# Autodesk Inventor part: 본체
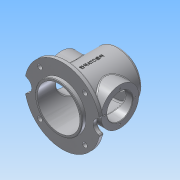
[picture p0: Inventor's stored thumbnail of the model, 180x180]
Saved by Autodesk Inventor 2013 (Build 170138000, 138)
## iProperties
Created: 2018-04
Part Number: 본체
Material: 알루미늄 6061
Document SubType Name: Modeling
Designer: Administrator
Density: 2.71 g/cm^3
Mass: 1151.24 g
Surface Area: 1200.36 cm^2
Volume: 424.812 cm^3
Author: Administrator
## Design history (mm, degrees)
sketch "스케치1"
  geometry: C1 r 50 at (0, 0); 1 further point
  constraints: 1 centre point, 1 coincident
  dimensions: "d1" = 100 diameter of C1
extrude "돌출1" new body sketch "스케치1" distance "d2" = 128; taper "d3" = 0 deg
hole "구멍1" diameter "d6" = 90; stored, may be unused: countersink angle "d10" = 90 deg, drill point angle "d12" = 0 deg; dims "d4" = 10, "d5" = 10, "d7" = 6, "d8" = 4, "d9" = 2, "d11" = 120
node "작업 평면1"
sketch "스케치2"
  geometry: C1 r 80 at (0, 0); C2 r 50 at (0, 0) reference; 1 further point
  constraints: 1 centre point, 1 coincident
  dimensions: "d14" = 160 diameter of C1
extrude "돌출2" join sketch "스케치2" distance "d15" = 10; taper "d16" = 0 deg
sketch "스케치3"
  geometry: C1 r 50 at (0, 0) reference; C2 r 15 at (-80, 0); C3 r 15 at (80, 0); A1 r 80 centre (0, 0) between (-80, 0) and (80, 0) reference
  constraints: 2 centre point, 2 horizontal alignment, 2 point on circle
  dimensions: "d17" = 30 diameter of C2; "d18" = 30 diameter of C3
extrude "돌출3" cut sketch "스케치3" stored distance "d19" = 10; taper "d20" = 0 deg
sketch "스케치4" dims "d21" = 135
  geometry: L1 (0, 50)-(0, 0); L2 (0, 0)-(-47.73, 47.73); C1 r 5 at (-47.73, 47.73); A1 r 80 centre (0, 0) between (78.594, 14.934) and (-78.594, 14.934) reference; 1 further point
  constraints: 4 end point, 2 coincident, 1 centre point, 1 vertical, 1 vertical alignment, 4 other
  dimensions: "d22" = 45 deg angle of L2 L1; "d24" = 10 diameter of C1
extrude "돌출4" cut sketch "스케치4" stored distance "d25" = 10; taper "d26" = 0 deg
node "작업 평면2"
sketch "스케치5"
  geometry: L1 (8, -14.934)-(8, -80) reference; C1 r 40 at (68, 0); 1 further point
  constraints: 1 centre point, 1 horizontal alignment
  dimensions: "d31" = 80 diameter of C1; "d33" = 60 distance from line of L1 C1.centre
extrude "돌출5" join sketch "스케치5" stored distance "d34" = 10; taper "d35" = 0 deg
sketch "스케치6"
  geometry: C1 r 40 at (0, 0) reference; 2 further points
  constraints: 1 coincident
hole "구멍2" sketch "스케치6" at (0, 0) diameter "d36" = 54; stored, may be unused: countersink angle "d40" = 90 deg, drill point angle "d42" = 0 deg; dims "d37" = 6, "d38" = 4, "d39" = 2, "d41" = 120
sketch "스케치7"
  geometry: C1 r 27 at (0, 0) reference; 2 further points
  constraints: 1 vertical alignment
  dimensions: "d43" = 32.5 distance of point (0, 32.5) C1.centre
hole "구멍3" sketch "스케치7" at (0, 32.5) diameter "d44" = 3.242; stored, may be unused: countersink angle "d48" = 90 deg, drill point angle "d50" = 118 deg; dims "d45" = 8, "d46" = 4, "d47" = 2, "d49" = 10
sketch "스케치8"
  geometry: C1 r 50 at (0, 0) reference; C2 r 40 at (0, 0)
  constraints: 1 centre point, 1 coincident
  dimensions: "d54" = 80 diameter of C2
extrude "돌출6" join sketch "스케치8" distance "d55" = 5; taper "d56" = 0 deg
hole "구멍4" diameter "d59" = 54; stored, may be unused: countersink angle "d63" = 90 deg, drill point angle "d65" = 118 deg; dims "d57" = 10, "d58" = 10, "d60" = 8, "d61" = 4, "d62" = 2, "d64" = 10
sketch "스케치9"
  geometry: C1 r 27 at (0, 0) reference; 1 further point
  constraints: 1 vertical alignment
  dimensions: "d66" = 32.5 distance of C1.centre point (0, 32.5)
hole "구멍5" sketch "스케치9" at (0, 32.5) diameter "d67" = 3.242; stored, may be unused: countersink angle "d71" = 90 deg, drill point angle "d73" = 118 deg; dims "d68" = 8, "d69" = 4, "d70" = 2, "d72" = 10
node "작업 평면3"
sketch "스케치10" dims "d3" = 0
  geometry: 2 further points
  constraints: 1 vertical alignment, 1 other
  dimensions: "d78" = 70 distance of point (0, 70) point (0, 0)
feature "엠보싱1" sketch "스케치10" dims "d2" = 128, "d79" = 0.5, "d80" = 0
fillet "모깎기1" dims "d81" = 5
fillet "모깎기2" dims "d82" = 3
fillet "모깎기3" dims "d83" = 3
fillet "모깎기4" dims "d84" = 3
fillet "모깎기5" dims "d85" = 3
chamfer "모따기1" distance "d86" = 1; stored, may be unused: second distance "d87" = 2, angle "d88" = 45 deg
chamfer "모따기2" distance "d89" = 1; stored, may be unused: second distance "d90" = 2, angle "d91" = 45 deg
node "솔리드1"
pattern_circular "원형 패턴1" dims angle "d28" = 360 deg
pattern_circular "원형 패턴2" dims angle "d52" = 360 deg
mirror "대칭1"
pattern_circular "원형 패턴3" dims angle "d75" = 360 deg
other parameters: "d30" = 62
